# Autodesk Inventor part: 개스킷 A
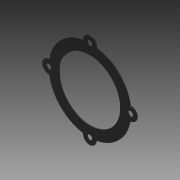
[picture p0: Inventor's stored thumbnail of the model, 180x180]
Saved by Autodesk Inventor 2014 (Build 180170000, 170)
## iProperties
Created: 2020-03
Part Number: 개스킷 A
Material: 고무
Document SubType Name: Modeling
Designer: mduedu
Density: 0.93 g/cm^3
Mass: 2.68337 g
Surface Area: 63.575 cm^2
Volume: 2.88534 cm^3
Appearance: Rubber - Black - Version 1.1
Author: mduedu
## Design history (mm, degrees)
sketch "스케치1" dims "d1" = 88
  geometry: C1 r 33 at (0, 0); C2 r 7 at (0, 44); C3 r 7 at (-38.105, -22); C4 r 7 at (38.105, -22); 2 further points
  constraints: 4 centre point, 2 coincident, 2 vertical alignment, 9 other
  dimensions: "d0" = 66 diameter of C1; "d2" = 14 diameter of C2; "d5" = 360 deg dimension on point (0, 0) C2.centre (derived)
extrude "돌출1" new body sketch "스케치1" distance "d7" = 1; taper "d8" = 0 deg
extrude "돌출2" join sketch "스케치1" stored distance "d17" = 10; taper "d18" = 0 deg
fillet "모깎기1" dims "d9" = 1
sketch "스케치2"
  geometry: C1 r 33 at (0, 0) reference; A1 r 44 centre (0, 0) between (-7.817, 43.3) and (7.817, 43.3) reference; A2 r 7 centre (0, 44) between (6.996, 44.249) and (-6.996, 44.249) reference; A3 r 1 centre (7.995, 44.284) between (6.996, 44.249) and (7.817, 43.3) reference; A4 r 1 centre (-7.995, 44.284) between (-7.817, 43.3) and (-6.996, 44.249) reference; 4 further points
hole "구멍1" sketch "스케치2" diameter "d10" = 5.5; stored, may be unused: countersink angle "d14" = 90 deg, drill point angle "d16" = 118 deg; dims "d11" = 6, "d12" = 10, "d13" = 5.7, "d15" = 8
node "솔리드1"
pattern_circular "원형 패턴1" dims "d20" = 360 deg
node "투영된 루프1"
